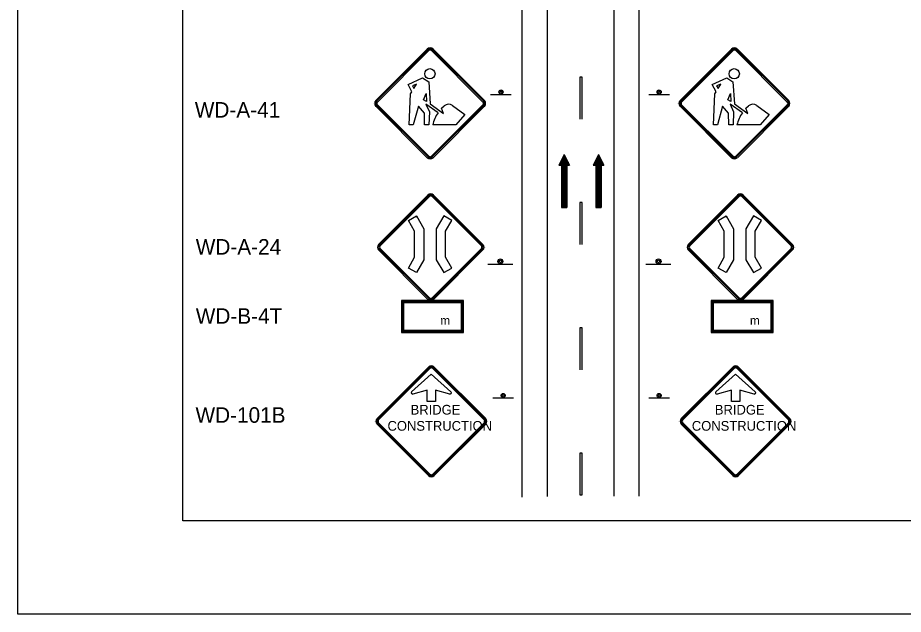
# Model space of a CAD drawing. Extents: x 1056 to 1280, y 240 to 519.
# Drawn here: x 1055.6 to 1158.2, y 239.8 to 308.9 of the extents above; entities that cross this region are included whole.
import ezdxf

# ---------------------------------------------------------------- set-up
doc = ezdxf.new("R2010")
doc.units = 0
for name, color, linetype in [('Level 10', 7, 'Continuous'), ('Level 17', 7, 'Continuous'), ('Level 44', 7, 'Continuous')]:
    doc.layers.add(name, color=color, linetype=linetype)

# ---------------------------------------------------------------- blocks, each defined once
blk = doc.blocks.new('WDA024')
at = {"layer": 'Level 17'}
for p, q in [((50.34, 50.34), (2.69, 2.69)), ((51.05, 49.64), (3.39, 1.98)), ((51.76, 48.94), (4.1, 1.27)), ((101.97, 1.27), (54.3, 48.94)), ((102.67, 1.98), (55.01, 49.64)), ((103.38, 2.69), (55.72, 50.34)), ((40.54, 24.59), (32.82, 20.13)), ((32.82, 20.13), (38.86, 9.73)), ((47.74, 12.11), (40.54, 24.59)), ((59.76, 12.11), (66.96, 24.59)), ((66.96, 24.59), (74.62, 20.13)), ((74.62, 20.13), (68.64, 9.73)), ((38.86, 9.73), (38.86, -15.46)), ((47.74, -17.84), (47.74, 12.11)), ((59.76, -17.84), (59.76, 12.11)), ((68.64, 9.73), (68.64, -15.46)), ((0, 0), (0, 0)), ((2.69, -2.69), (50.34, -50.35)), ((3.39, -1.98), (51.05, -49.64)), ((4.1, -1.27), (51.76, -48.93)), ((54.3, -48.93), (101.97, -1.27)), ((55.01, -49.64), (102.67, -1.98)), ((55.72, -50.35), (103.38, -2.69)), ((38.86, -15.46), (32.82, -25.86)), ((68.64, -15.46), (74.62, -25.86)), ((40.54, -30.27), (47.74, -17.84)), ((66.96, -30.27), (59.76, -17.84)), ((32.82, -25.86), (40.54, -30.27)), ((74.62, -25.86), (66.96, -30.27)), ((66.96, -30.27), (67.36, -28.58))]:
    blk.add_line(p, q, dxfattribs=at)
for centre, radius, start, end in [((53.03, 47.66), 3.8, 45, 135), ((53.03, 47.66), 2.8, 45, 135), ((53.03, 47.66), 1.8, 45, 135), ((5.37, 0), 3.8, 135, 225), ((5.37, 0), 2.8, 135, 225), ((5.37, 0), 1.8, 135, 225), ((100.69, 0), 1.8, 315, 45), ((100.69, 0), 2.8, 315, 45), ((100.69, 0), 3.8, 315, 45), ((53.03, -47.66), 3.8, 225, 315), ((53.03, -47.66), 2.8, 225, 315), ((53.03, -47.66), 1.8, 225, 315)]:
    blk.add_arc(centre, radius, start, end, dxfattribs=at)
blk = doc.blocks.new('WDB04T')
at = {"layer": 'Level 17'}
for points in [[(60.004, 0.004), (0.004, 0.004), (0.004, -30.671), (60.004, -30.671)], [(59.004, -0.996), (1.004, -0.996), (1.004, -29.671), (59.004, -29.671)], [(58.004, -1.996), (2.004, -1.996), (2.004, -28.671), (58.004, -28.671)]]:
    blk.add_lwpolyline(points, close=True, dxfattribs=at)
blk.add_text('m', height=8.373, dxfattribs=at).set_placement((37.562, -23.321))

msp = doc.modelspace()

# ---------------------------------------------------------------- linework, layer by layer
at = {"layer": 'Level 10'}
for p, q in [((1114.04, 303.07), (1114.04, 384.85)), ((1124.69, 303.09), (1124.69, 374.01)), ((1116.95, 303.07), (1116.95, 361.85)), ((1127.59, 253.5), (1127.59, 329.09)), ((1103.03, 305.29), (1097.07, 299.33)), ((1103.12, 305.2), (1097.16, 299.24)), ((1103.21, 305.11), (1097.25, 299.15)), ((1109.48, 299.15), (1103.53, 305.11)), ((1109.57, 299.24), (1103.61, 305.2)), ((1109.66, 299.33), (1103.7, 305.29)), ((1138.3, 305.29), (1132.34, 299.33)), ((1138.38, 305.2), (1132.43, 299.24)), ((1138.47, 305.11), (1132.51, 299.15)), ((1144.75, 299.15), (1138.79, 305.11)), ((1144.84, 299.24), (1138.88, 305.2)), ((1144.92, 299.33), (1138.97, 305.29)), ((1114.04, 253.4), (1114.04, 303.07)), ((1116.95, 253.45), (1116.95, 303.07)), ((1124.69, 253.5), (1124.69, 303.09)), ((1120.7, 302.02), (1120.7, 297.18)), ((1121, 302.02), (1120.7, 302.02)), ((1121, 297.18), (1121, 302.02)), ((1096.74, 298.99), (1096.74, 298.99)), ((1097.16, 298.75), (1103.12, 292.79)), ((1097.25, 298.83), (1103.21, 292.88)), ((1103.53, 292.88), (1109.48, 298.83)), ((1103.61, 292.79), (1109.57, 298.75)), ((1104.67, 298.43), (1104.98, 298.7)), ((1104.67, 298.43), (1104.98, 298.7)), ((1105.96, 298.75), (1107.39, 297.71)), ((1105.96, 298.75), (1107.39, 297.71)), ((1132, 298.99), (1132, 298.99)), ((1132.43, 298.75), (1138.38, 292.79)), ((1132.51, 298.83), (1138.47, 292.88)), ((1138.79, 292.88), (1144.75, 298.83)), ((1138.88, 292.79), (1144.84, 298.75)), ((1139.94, 298.43), (1140.25, 298.7)), ((1139.94, 298.43), (1140.25, 298.7)), ((1141.23, 298.75), (1142.66, 297.71)), ((1141.23, 298.75), (1142.66, 297.71)), ((1097.07, 298.66), (1103.03, 292.7)), ((1103.7, 292.7), (1109.66, 298.66)), ((1132.34, 298.66), (1138.3, 292.7)), ((1138.97, 292.7), (1144.92, 298.66)), ((1118.89, 293.09), (1118.28, 291.86)), ((1118.66, 292.62), (1118.66, 286.95)), ((1118.74, 292.78), (1118.74, 286.95)), ((1118.82, 292.93), (1118.82, 286.95)), ((1118.89, 293.09), (1118.89, 286.95)), ((1118.89, 293.09), (1119.51, 291.86)), ((1118.97, 292.93), (1118.97, 286.95)), ((1119.05, 292.78), (1119.05, 286.95)), ((1119.12, 292.62), (1119.12, 286.95)), ((1122.88, 293.09), (1122.26, 291.86)), ((1122.65, 292.62), (1122.65, 286.95)), ((1122.72, 292.78), (1122.72, 286.95)), ((1122.8, 292.93), (1122.8, 286.95)), ((1122.88, 293.09), (1122.88, 286.95)), ((1122.88, 293.09), (1123.49, 291.86)), ((1122.95, 292.93), (1122.95, 286.95)), ((1123.03, 292.78), (1123.03, 286.95)), ((1123.11, 292.62), (1123.11, 286.95)), ((1118.28, 291.86), (1118.59, 291.86)), ((1118.36, 292.01), (1118.36, 291.86)), ((1118.43, 292.17), (1118.43, 291.86)), ((1118.51, 292.32), (1118.51, 291.86)), ((1118.59, 292.47), (1118.59, 286.95)), ((1118.59, 291.86), (1118.59, 286.95)), ((1119.2, 292.47), (1119.2, 286.95)), ((1119.2, 291.86), (1119.2, 286.95)), ((1119.2, 291.86), (1119.51, 291.86)), ((1119.28, 292.32), (1119.28, 291.86)), ((1119.35, 292.17), (1119.35, 291.86)), ((1119.43, 292.01), (1119.43, 291.86)), ((1122.26, 291.86), (1122.57, 291.86)), ((1122.34, 292.01), (1122.34, 291.86)), ((1122.42, 292.17), (1122.42, 291.86)), ((1122.49, 292.32), (1122.49, 291.86)), ((1122.57, 292.47), (1122.57, 286.95)), ((1122.57, 291.86), (1122.57, 286.95)), ((1123.18, 292.47), (1123.18, 286.95)), ((1123.18, 291.86), (1123.18, 286.95)), ((1123.18, 291.86), (1123.49, 291.86)), ((1123.26, 292.32), (1123.26, 291.86)), ((1123.34, 292.17), (1123.34, 291.86)), ((1123.41, 292.01), (1123.41, 291.86)), ((1120.7, 287.5), (1120.7, 282.67)), ((1121, 287.5), (1120.7, 287.5)), ((1121, 282.67), (1121, 287.5)), ((1118.59, 286.95), (1119.2, 286.95)), ((1122.57, 286.95), (1123.18, 286.95)), ((1120.7, 272.99), (1120.7, 268.15)), ((1121, 272.99), (1120.7, 272.99)), ((1121, 268.15), (1121, 272.99)), ((1097.21, 262.5), (1103.17, 268.46)), ((1097.3, 262.42), (1103.26, 268.37)), ((1097.39, 262.33), (1103.34, 268.28)), ((1103.66, 268.28), (1109.62, 262.33)), ((1103.75, 268.37), (1109.71, 262.42)), ((1103.84, 268.46), (1109.8, 262.5)), ((1132.47, 262.5), (1138.43, 268.46)), ((1132.56, 262.42), (1138.52, 268.37)), ((1132.65, 262.33), (1138.61, 268.28)), ((1138.93, 268.28), (1144.88, 262.33)), ((1139.01, 268.37), (1144.97, 262.42)), ((1139.1, 268.46), (1145.06, 262.5)), ((1101.35, 265.33), (1101.35, 265.33)), ((1101.35, 265.33), (1101.35, 265.33)), ((1101.35, 265.33), (1101.35, 265.33)), ((1136.62, 265.33), (1136.62, 265.33)), ((1136.62, 265.33), (1136.62, 265.33)), ((1136.62, 265.33), (1136.62, 265.33)), ((1096.87, 262.17), (1096.87, 262.17)), ((1103.17, 255.88), (1097.21, 261.83)), ((1103.26, 255.96), (1097.3, 261.92)), ((1103.34, 256.05), (1097.39, 262.01)), ((1109.62, 262.01), (1103.66, 256.05)), ((1109.71, 261.92), (1103.75, 255.96)), ((1109.8, 261.83), (1103.84, 255.88)), ((1132.14, 262.17), (1132.14, 262.17)), ((1138.43, 255.88), (1132.47, 261.83)), ((1138.52, 255.96), (1132.56, 261.92)), ((1138.61, 256.05), (1132.65, 262.01)), ((1144.88, 262.01), (1138.93, 256.05)), ((1144.97, 261.92), (1139.01, 255.96)), ((1145.06, 261.83), (1139.1, 255.88)), ((1120.7, 258.48), (1120.7, 253.64)), ((1121, 258.48), (1120.7, 258.48)), ((1121, 253.64), (1121, 258.48)), ((1120.7, 253.64), (1121, 253.64))]:
    msp.add_line(p, q, dxfattribs=at)
for points in [[(1055.56, 518.82), (1271.56, 518.82), (1271.56, 239.82), (1055.56, 239.82)], [(1074.69, 508.01), (1261.56, 508.01), (1261.56, 250.63), (1074.69, 250.63)], [(1101.3, 301.03), (1101.47, 300.72), (1101.8, 301.24)], [(1136.56, 301.03), (1136.74, 300.72), (1137.06, 301.24)], [(1102.59, 299.42), (1102.89, 300.16), (1102.93, 299.2)], [(1137.85, 299.42), (1138.16, 300.16), (1138.2, 299.2)]]:
    msp.add_lwpolyline(points, close=True, dxfattribs=at)
for points in [[(1104.3, 297.9), (1102.85, 298.89), (1103.28, 298.02), (1103.22, 296.5), (1102.72, 296.5), (1102.69, 297.87), (1102, 298.68), (1101.39, 296.5), (1100.95, 296.5), (1101.07, 300.09), (1101.24, 300.34), (1100.8, 301.18), (1102.48, 301.94), (1103.2, 301.51), (1103.37, 298.94), (1104.91, 297.83), (1104.67, 298.43)], [(1139.56, 297.9), (1138.12, 298.89), (1138.54, 298.02), (1138.49, 296.5), (1137.99, 296.5), (1137.96, 297.87), (1137.26, 298.68), (1136.65, 296.5), (1136.22, 296.5), (1136.34, 300.09), (1136.51, 300.34), (1136.06, 301.18), (1137.75, 301.94), (1138.46, 301.51), (1138.63, 298.94), (1140.18, 297.83), (1139.94, 298.43)], [(1107.39, 297.71), (1106.34, 296.5), (1103.66, 296.5)], [(1142.66, 297.71), (1141.6, 296.5), (1138.92, 296.5)], [(1101.22, 265.58), (1103.5, 267.65), (1105.78, 265.58)], [(1101.22, 265.58), (1103.5, 267.65), (1105.78, 265.58)], [(1101.22, 265.58), (1103.5, 267.65), (1105.78, 265.58)], [(1136.49, 265.58), (1138.77, 267.65), (1141.05, 265.58)], [(1136.49, 265.58), (1138.77, 267.65), (1141.05, 265.58)], [(1136.49, 265.58), (1138.77, 267.65), (1141.05, 265.58)], [(1105.65, 265.33), (1103.97, 265.76), (1103.97, 264.46), (1103.03, 264.46), (1103.03, 265.76), (1101.35, 265.33)], [(1105.65, 265.33), (1103.97, 265.76), (1103.97, 264.46), (1103.03, 264.46), (1103.03, 265.76), (1101.35, 265.33)], [(1105.65, 265.33), (1103.97, 265.76), (1103.97, 264.46), (1103.03, 264.46), (1103.03, 265.76), (1101.35, 265.33)], [(1140.91, 265.33), (1139.24, 265.76), (1139.24, 264.46), (1138.29, 264.46), (1138.29, 265.76), (1136.62, 265.33)], [(1140.91, 265.33), (1139.24, 265.76), (1139.24, 264.46), (1138.29, 264.46), (1138.29, 265.76), (1136.62, 265.33)], [(1140.91, 265.33), (1139.24, 265.76), (1139.24, 264.46), (1138.29, 264.46), (1138.29, 265.76), (1136.62, 265.33)]]:
    msp.add_lwpolyline(points, dxfattribs=at)
for centre in [(1103.34, 302.43), (1138.61, 302.43)]:
    msp.add_circle(centre, 0.593, dxfattribs=at)
for centre, radius, start, end in [((1103.37, 304.95), 0.475, 45, 135), ((1103.37, 304.95), 0.35, 45, 135), ((1103.37, 304.95), 0.225, 45, 135), ((1138.63, 304.95), 0.475, 45, 135), ((1138.63, 304.95), 0.35, 45, 135), ((1138.63, 304.95), 0.225, 45, 135), ((1097.41, 298.99), 0.475, 135, 225), ((1097.41, 298.99), 0.35, 135, 225), ((1097.41, 298.99), 0.225, 135, 225), ((1105.5, 298.12), 0.78, 53.9362, 131.97), ((1105.5, 298.12), 0.78, 53.9362, 131.97), ((1109.32, 298.99), 0.225, 315, 45), ((1109.32, 298.99), 0.35, 315, 45), ((1109.32, 298.99), 0.475, 315, 45), ((1132.67, 298.99), 0.475, 135, 225), ((1132.67, 298.99), 0.35, 135, 225), ((1132.67, 298.99), 0.225, 135, 225), ((1140.77, 298.12), 0.78, 53.9362, 131.97), ((1140.77, 298.12), 0.78, 53.9362, 131.97), ((1144.59, 298.99), 0.225, 315, 45), ((1144.59, 298.99), 0.35, 315, 45), ((1144.59, 298.99), 0.475, 315, 45), ((1107.27, 295.71), 3.7, 143.5617, 167.6366), ((1142.54, 295.71), 3.7, 143.5617, 167.6366), ((1103.37, 293.04), 0.475, 225, 315), ((1103.37, 293.04), 0.35, 225, 315), ((1103.37, 293.04), 0.225, 225, 315), ((1138.63, 293.04), 0.475, 225, 315), ((1138.63, 293.04), 0.35, 225, 315), ((1138.63, 293.04), 0.225, 225, 315), ((1103.5, 268.13), 0.475, 45, 135), ((1103.5, 268.13), 0.35, 45, 135), ((1103.5, 268.13), 0.225, 45, 135), ((1138.77, 268.13), 0.475, 45, 135), ((1138.77, 268.13), 0.35, 45, 135), ((1138.77, 268.13), 0.225, 45, 135), ((1101.32, 265.47), 0.143, 132.3048, 284.4075), ((1101.32, 265.47), 0.143, 132.3048, 284.4075), ((1101.32, 265.47), 0.143, 132.3048, 284.4075), ((1105.68, 265.47), 0.143, 255.5925, 47.6952), ((1105.68, 265.47), 0.143, 255.5925, 47.6952), ((1105.68, 265.47), 0.143, 255.5925, 47.6952), ((1136.58, 265.47), 0.143, 132.3048, 284.4075), ((1136.58, 265.47), 0.143, 132.3048, 284.4075), ((1136.58, 265.47), 0.143, 132.3048, 284.4075), ((1140.95, 265.47), 0.143, 255.5925, 47.6952), ((1140.95, 265.47), 0.143, 255.5925, 47.6952), ((1140.95, 265.47), 0.143, 255.5925, 47.6952), ((1097.55, 262.17), 0.475, 135, 225), ((1097.55, 262.17), 0.35, 135, 225), ((1097.55, 262.17), 0.225, 135, 225), ((1109.46, 262.17), 0.225, 315, 45), ((1109.46, 262.17), 0.35, 315, 45), ((1109.46, 262.17), 0.475, 315, 45), ((1132.81, 262.17), 0.475, 135, 225), ((1132.81, 262.17), 0.35, 135, 225), ((1132.81, 262.17), 0.225, 135, 225), ((1144.72, 262.17), 0.225, 315, 45), ((1144.72, 262.17), 0.35, 315, 45), ((1144.72, 262.17), 0.475, 315, 45), ((1103.5, 256.21), 0.475, 225, 315), ((1103.5, 256.21), 0.35, 225, 315), ((1103.5, 256.21), 0.225, 225, 315), ((1138.77, 256.21), 0.475, 225, 315), ((1138.77, 256.21), 0.35, 225, 315), ((1138.77, 256.21), 0.225, 225, 315)]:
    msp.add_arc(centre, radius, start, end, dxfattribs=at)
at = {"layer": 'Level 44'}
for p, q in [((1110.37, 300.04), (1112.76, 300.04)), ((1128.69, 300.04), (1131.09, 300.04)), ((1110.05, 280.37), (1112.95, 280.37)), ((1128.37, 280.37), (1131.27, 280.37)), ((1110.62, 264.89), (1113.02, 264.89)), ((1128.69, 264.89), (1131.09, 264.89))]:
    msp.add_line(p, q, dxfattribs=at)
for centre, radius in [((1111.57, 300.31), 0.24), ((1111.57, 300.31), 0.12), ((1129.9, 300.31), 0.24), ((1129.9, 300.31), 0.12), ((1111.5, 280.69), 0.29), ((1111.5, 280.69), 0.145), ((1129.83, 280.69), 0.29), ((1129.83, 280.69), 0.145), ((1111.83, 265.16), 0.24), ((1111.83, 265.16), 0.12), ((1129.9, 265.16), 0.24), ((1129.9, 265.16), 0.12)]:
    msp.add_circle(centre, radius, dxfattribs=at)

# ---------------------------------------------------------------- block references
at = {"layer": 'Level 17', "xscale": 0.12, "yscale": 0.12, "rotation": 179.99999999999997}
for p in [(1109.8, 282.34), (1145.69, 282.34)]:
    msp.add_blockref('WDA024', p, dxfattribs=at)
at = {"layer": 'Level 17', "xscale": 0.12, "yscale": 0.12}
for p in [(1100.04, 276.15), (1135.93, 276.15)]:
    msp.add_blockref('WDB04T', p, dxfattribs=at)

# ---------------------------------------------------------------- texts
at = {"layer": 'Level 10'}
for s, height, p in [('WD-A-41', 1.8, (1076.09, 297.35)), ('WD-A-24', 1.8, (1076.2, 281.48)), ('WD-B-4T', 1.8, (1076.2, 273.47)), ('WD-101B', 1.8, (1076.17, 262)), ('BRIDGE', 1.125, (1101.1, 262.95)), ('BRIDGE', 1.125, (1136.36, 262.95)), ('CONSTRUCTION', 1.125, (1098.42, 261.08)), ('CONSTRUCTION', 1.125, (1133.69, 261.08))]:
    msp.add_text(s, height=height, dxfattribs=at).set_placement(p)

doc.saveas('drawing.dxf')
